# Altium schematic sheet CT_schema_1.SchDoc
size 666 x 614 mm
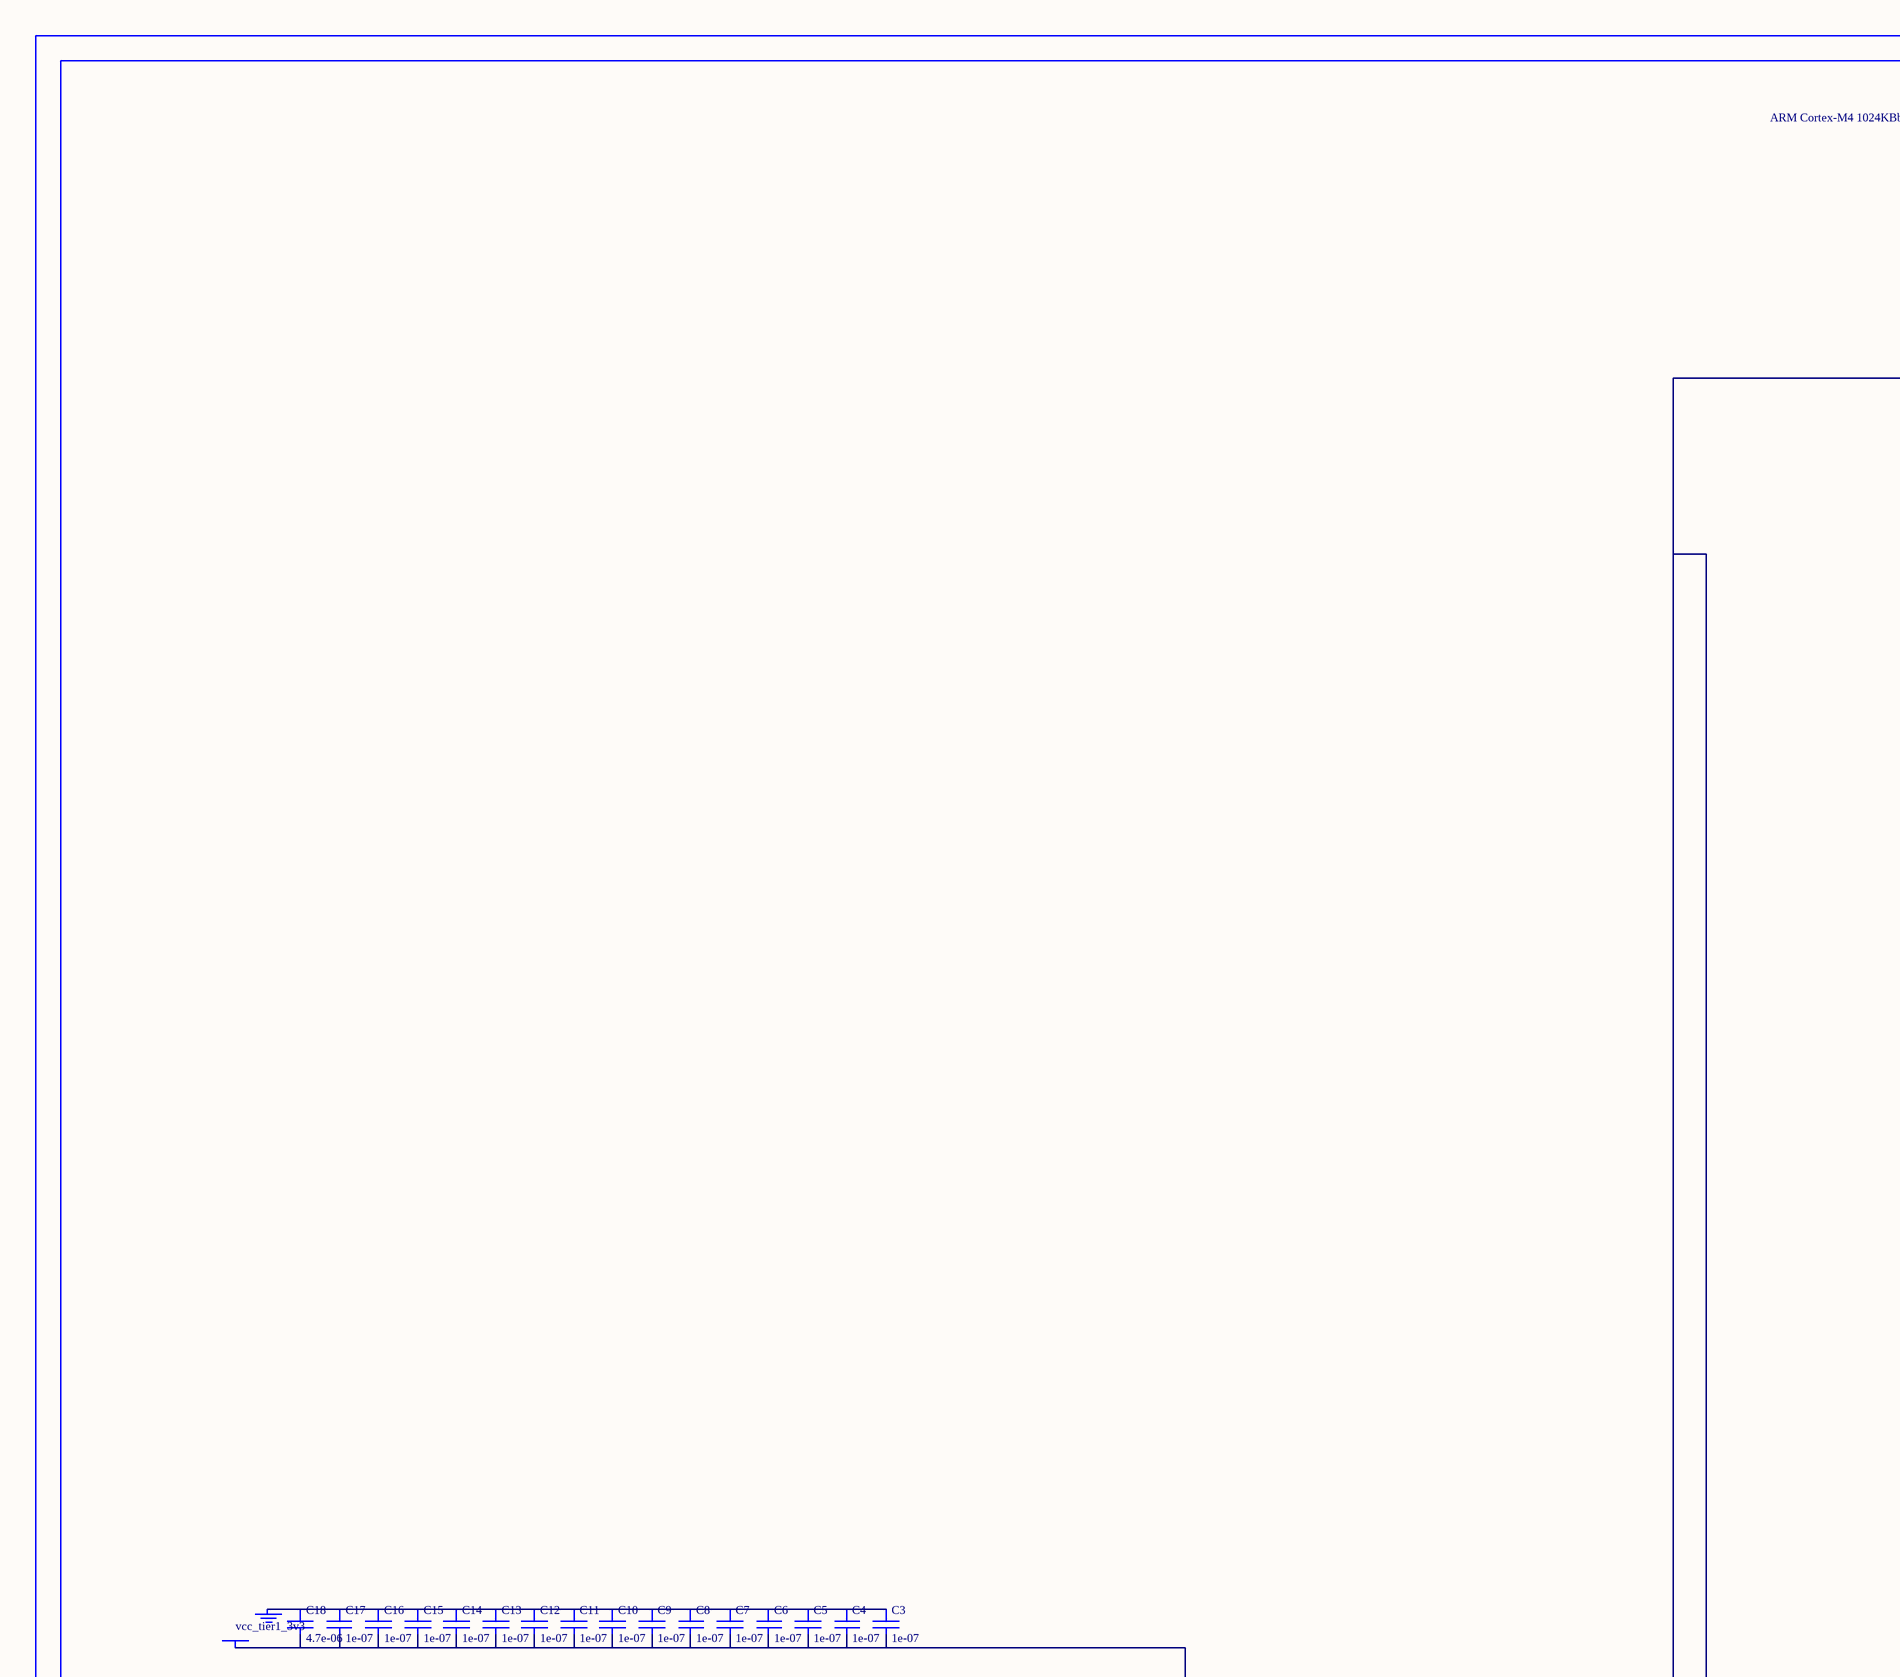
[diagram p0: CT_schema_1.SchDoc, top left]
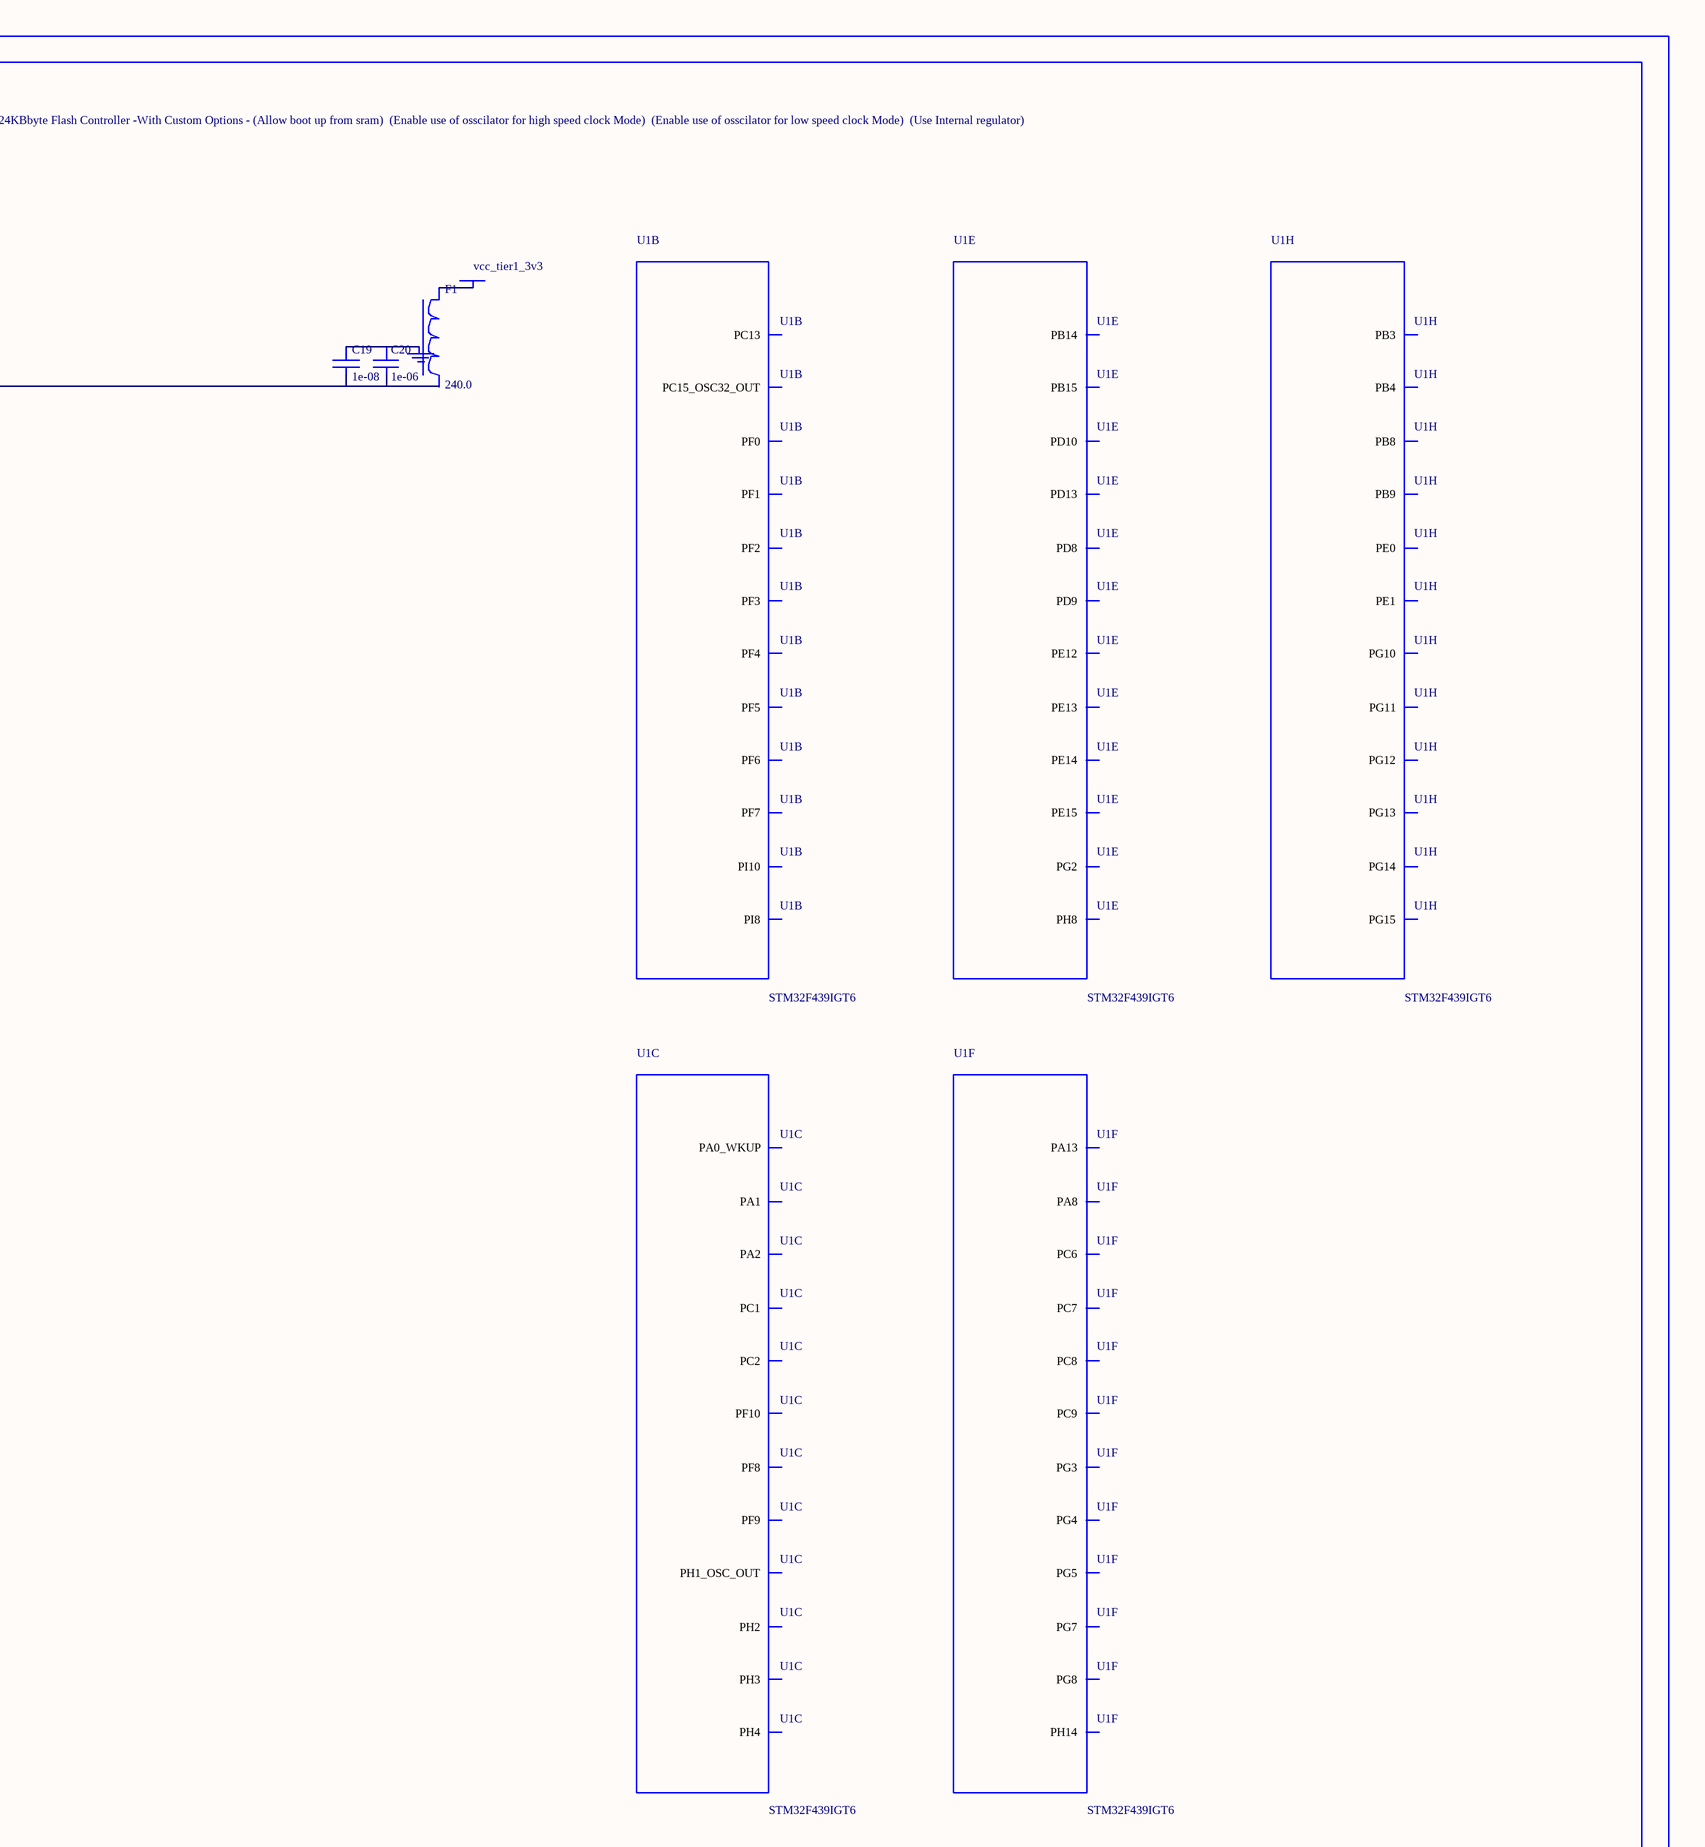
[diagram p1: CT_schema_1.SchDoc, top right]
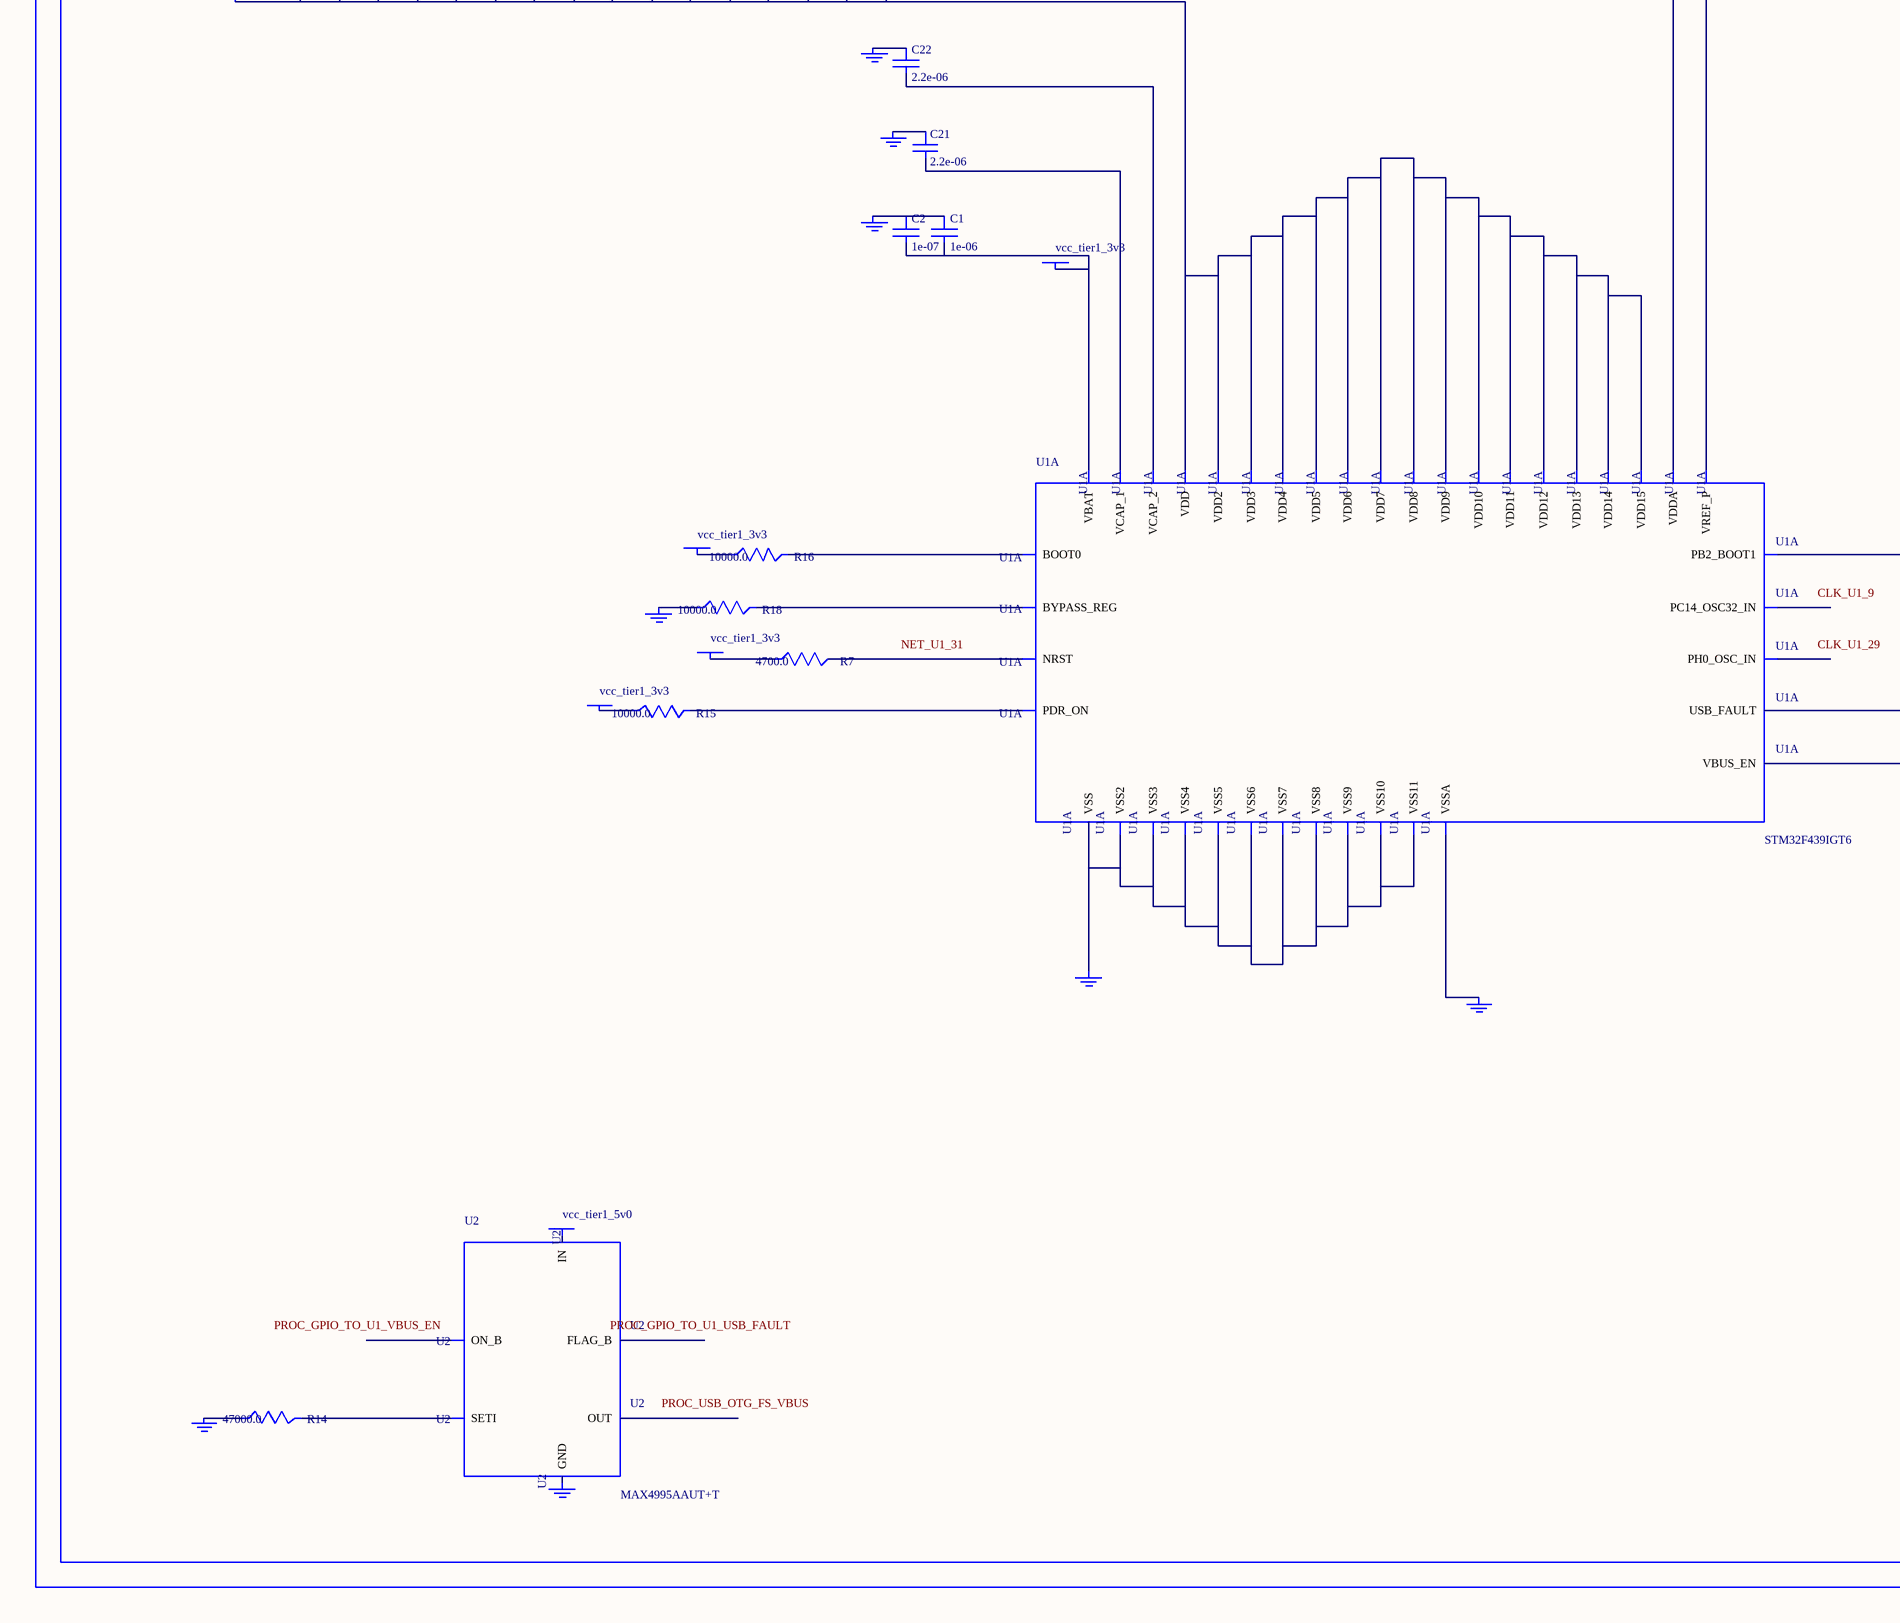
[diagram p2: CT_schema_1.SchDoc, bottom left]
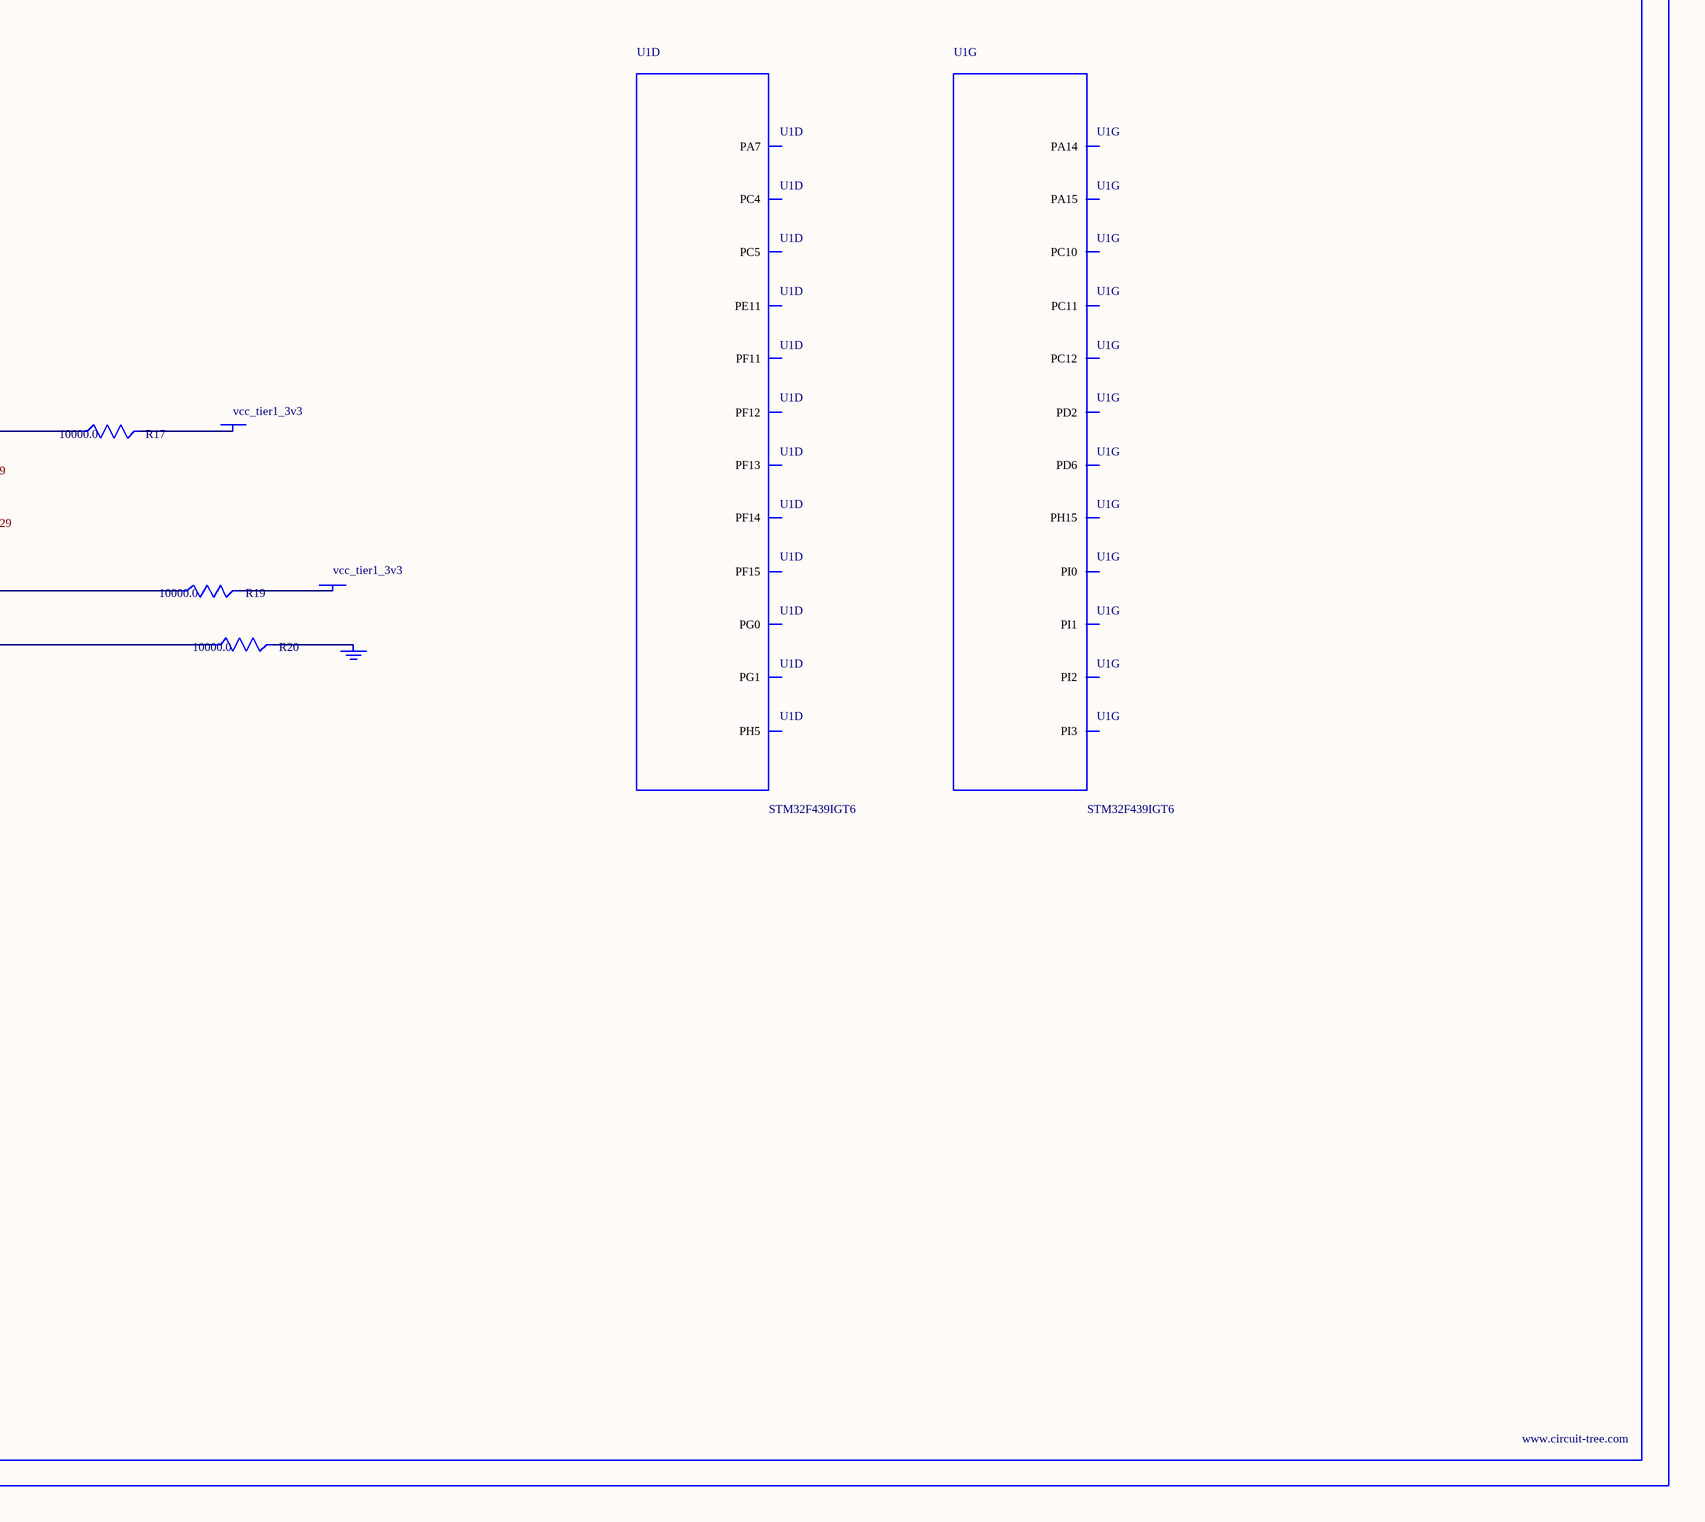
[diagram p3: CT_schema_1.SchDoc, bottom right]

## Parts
BORDER0  (no value)
C1  1e-06  [C0603]
C2  1e-07  [C0603]
C3  1e-07  [C0603]
C4  1e-07  [C0603]
C5  1e-07  [C0603]
C6  1e-07  [C0603]
C7  1e-07  [C0603]
C8  1e-07  [C0603]
C9  1e-07  [C0603]
C10  1e-07  [C0603]
C11  1e-07  [C0603]
C12  1e-07  [C0603]
C13  1e-07  [C0603]
C14  1e-07  [C0603]
C15  1e-07  [C0603]
C16  1e-07  [C0603]
C17  1e-07  [C0603]
C18  4.7e-06  [C0603]
C19  1e-08  [C0603]
C20  1e-06  [C0603]
C21  2.2e-06  [C0603]
C22  2.2e-06  [C0603]
F1  240.0  [L0603]
GND_INSTANCE_0_0  (no value)
GND_INSTANCE_0_1  (no value)
GND_INSTANCE_0_2  (no value)
GND_INSTANCE_0_3  (no value)
GND_INSTANCE_0_4  (no value)
GND_INSTANCE_0_5  (no value)
GND_INSTANCE_0_6  (no value)
GND_INSTANCE_0_7  (no value)
GND_INSTANCE_0_8  (no value)
GND_INSTANCE_0_9  (no value)
GND_INSTANCE_0_10  (no value)
POWER_INSTANCE_0_0  vcc_tier1_3v3
POWER_INSTANCE_0_1  vcc_tier1_3v3
POWER_INSTANCE_0_2  vcc_tier1_3v3
POWER_INSTANCE_0_3  vcc_tier1_3v3
POWER_INSTANCE_0_4  vcc_tier1_3v3
POWER_INSTANCE_0_5  vcc_tier1_3v3
POWER_INSTANCE_0_6  vcc_tier1_3v3
POWER_INSTANCE_0_7  vcc_tier1_3v3
POWER_INSTANCE_0_8  vcc_tier1_5v0
R7  4700.0  [R0603]
R14  47000.0  [R0603]
R15  10000.0  [R0603]
R16  10000.0  [R0603]
R17  10000.0  [R0603]
R18  10000.0  [R0603]
R19  10000.0  [R0603]
R20  10000.0  [R0603]
U1  STM32F439IGT6  [LQFP176]  (parts A,B,C,D,E,F,G,H of 14)
U2  MAX4995AAUT+T  [SOT-23-6]

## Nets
NetC1_1: C1.1 C2.1 GND_INSTANCE_0_1.0(GND)
NetC1_2: C1.2 C2.2 POWER_INSTANCE_0_1.0(PWR) U1.6(VBAT)
NetC3_1: C3.1 C4.1 C5.1 C6.1 C7.1 C8.1 C9.1 C10.1 C11.1 C12.1 C13.1 C14.1 C15.1 C16.1 C17.1 C18.1 GND_INSTANCE_0_2.0(GND)
NetC3_2: C3.2 C4.2 C5.2 C6.2 C7.2 C8.2 C9.2 C10.2 C11.2 C12.2 C13.2 C14.2 C15.2 C16.2 C17.2 C18.2 POWER_INSTANCE_0_2.0(PWR) U1.15(VDD) U1.23(VDD2) U1.36(VDD3) U1.49(VDD4) U1.62(VDD5) U1.72(VDD6) U1.82(VDD7) U1.91(VDD8) U1.103(VDD9) U1.114(VDD10) U1.127(VDD11) U1.136(VDD12) U1.149(VDD13) U1.159(VDD14) U1.172(VDD15)
NetC19_1: C19.1 C20.1 GND_INSTANCE_0_4.0(GND)
NetC19_2: C19.2 C20.2 U1.38(VREF_P) U1.39(VDDA)
NetC21_1: C21.1 GND_INSTANCE_0_6.0(GND)
NetC21_2: C21.2 U1.81(VCAP_1)
NetC22_1: C22.1 GND_INSTANCE_0_7.0(GND)
NetC22_2: C22.2 U1.125(VCAP_2)
NetF1_1: F1.1 POWER_INSTANCE_0_3.0(PWR)
NetGND_INSTANCE_0_0_0: GND_INSTANCE_0_0.0(GND) R20.2
NetGND_INSTANCE_0_3_0: GND_INSTANCE_0_3.0(GND) U1.37(VSSA)
NetGND_INSTANCE_0_5_0: GND_INSTANCE_0_5.0(GND) R18.1
NetGND_INSTANCE_0_8_0: GND_INSTANCE_0_8.0(GND) U1.14(VSS) U1.22(VSS2) U1.61(VSS3) U1.71(VSS4) U1.90(VSS5) U1.102(VSS6) U1.113(VSS7) U1.126(VSS8) U1.135(VSS9) U1.148(VSS10) U1.158(VSS11)
NetGND_INSTANCE_0_9_0: GND_INSTANCE_0_9.0(GND) R14.1
NetPOWER_INSTANCE_0_0_0: POWER_INSTANCE_0_0.0(PWR) R19.2
NetPOWER_INSTANCE_0_4_0: POWER_INSTANCE_0_4.0(PWR) R17.2
NetPOWER_INSTANCE_0_5_0: POWER_INSTANCE_0_5.0(PWR) R16.1
NetPOWER_INSTANCE_0_6_0: POWER_INSTANCE_0_6.0(PWR) R15.1
NetPOWER_INSTANCE_0_7_0: POWER_INSTANCE_0_7.0(PWR) R7.1
NetR7_2: R7.2 U1.31(NRST)
NetR14_2: R14.2 U2.3(SETI)
NetR15_2: R15.2 U1.171(PDR_ON)
NetR16_2: R16.2 U1.166(BOOT0)
NetR17_1: R17.1 U1.58(PB2_BOOT1)
NetR18_2: R18.2 U1.48(BYPASS_REG)
NetR19_1: R19.1 U1.2(USB_FAULT)
NetR20_1: R20.1 U1.1(VBUS_EN)

Not connected (* = marked no-connect by the designer): F1 2; GND_INSTANCE_0_10 0(GND); POWER_INSTANCE_0_8 0(PWR); U1 7(PI8) 8(PC13) 9(PC14_OSC32_IN) 10(PC15_OSC32_OUT) 12(PI10) 16(PF0) 17(PF1) 18(PF2) 19(PF3) 20(PF4) 21(PF5) 24(PF6) 25(PF7) 26(PF8) 27(PF9) 28(PF10) 29(PH0_OSC_IN) 30(PH1_OSC_OUT) 33(PC1) 34(PC2) 40(PA0_WKUP) 41(PA1) 42(PA2) 43(PH2) 44(PH3) 45(PH4) 46(PH5) 53(PA7) 54(PC4) 55(PC5) 59(PF11) 60(PF12) 63(PF13) 64(PF14) 65(PF15) 66(PG0) 67(PG1) 74(PE11) 75(PE12) 76(PE13) 77(PE14) 78(PE15) 85(PH8) 94(PB14) 95(PB15) 96(PD8) 97(PD9) 98(PD10) 101(PD13) 106(PG2) 107(PG3) 108(PG4) 109(PG5) 111(PG7) 112(PG8) 115(PC6) 116(PC7) 117(PC8) 118(PC9) 119(PA8) 124(PA13) 129(PH14) 130(PH15) 131(PI0) 132(PI1) 133(PI2) 134(PI3) 137(PA14) 138(PA15) 139(PC10) 140(PC11) 141(PC12) 144(PD2) 150(PD6) 153(PG10) 154(PG11) 155(PG12) 156(PG13) 157(PG14) 160(PG15) 161(PB3) 162(PB4) 167(PB8) 168(PB9) 169(PE0) 170(PE1); U2 1(OUT) 2(GND) 4(ON_B) 5(IN) 6(FLAG_B)

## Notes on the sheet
- Labels drawn without touching a wire or pin: CLK_U1_9, CLK_U1_29, NET_U1_31, PROC_GPIO_TO_U1_USB_FAULT, PROC_GPIO_TO_U1_VBUS_EN, PROC_USB_OTG_FS_VBUS

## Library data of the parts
BORDER0 = BORDER_PAGE0
C1 C20 = C0603C105K3RACTU
C2-C17 = 06035C104K4Z2A
C18 = GRM188R6YA475KE15D
C19 = 06035C103K4Z2A
C21 C22 = C0603C225K8RACTU
F1 = Z0603C241ASMST
GND_INSTANCE_0_0-GND_INSTANCE_0_10 = GND
POWER_INSTANCE_0_0-POWER_INSTANCE_0_8 = PWR
R7 = RC0603JR-074K7L
R14 = RC0603JR-0747KL
R15-R20 = RC0603JR-0710KL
